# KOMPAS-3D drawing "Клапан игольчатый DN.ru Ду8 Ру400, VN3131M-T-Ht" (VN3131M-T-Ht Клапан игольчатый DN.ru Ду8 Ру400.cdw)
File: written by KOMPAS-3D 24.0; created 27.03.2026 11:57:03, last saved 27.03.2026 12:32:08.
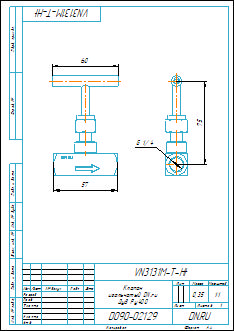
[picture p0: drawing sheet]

Document properties: Автор: Илья; Форматы листов документа: A4; Полное имя файла: VN3232M-T-Ht Клапан игольчатый DN.ru Ду8 Ру400.cdw; Масса: 0.35; Наименование: Клапан игольчатый DN.ru Ду8 Ру400; Количество листов документа: 1; Примечание: D090-02129

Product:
- Body: Body3  | qty 1
    Масса: 0.248386
- Part/product: Клапан игольчатый DN.ru Ду8 Ру400  | designation VN3131M-T-Ht
    Масса: 0.35
    Раздел спецификации: Прочие изделия
    Форматы листов документа: A4
    Примечание: D090-02129

Views: Проекционный вид 2
Referenced files in D:\Обмен\Заказы с фриланса\DN.ru\VNxxM-T-Ht Клапан игольчатый DN.ru Ду8-50 Ру400\VN3232M-T-Ht Клапан игольчатый DN.ru Ду8-50 Ру400\DN8\: VN3232M-T-Ht Клапан игольчатый DN.ru Ду8 Ру400.m3d, VN3232M-T-Ht Клапан игольчатый DN.ru Ду8 Ру400.cdw
Referenced files in D:\Обмен\Заказы с фриланса\DN.ru\VNxxM-T-Ht Клапан игольчатый DN.ru Ду8-50 Ру400\VN3131M-T-Ht Клапан игольчатый DN.ru Ду8-50 Ру400\DN8\: VN3131M-T-Ht Клапан игольчатый DN.ru Ду8 Ру400.m3d
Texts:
  VN3131M-T-Ht
  Клапан
  игольчатый DN.ru
  Ду8 Ру400
  Body3
  Клапан игольчатый DN.ru Ду8 Ру400
  VN3131M-T-Ht Клапан игольчатый DN.ru Ду8 Ру400
Dimensions and other numbers on the sheet: 0; 3; 4; 75; 1:1; 1; 2; 0,35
